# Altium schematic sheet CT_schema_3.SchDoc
size 283 x 173 mm
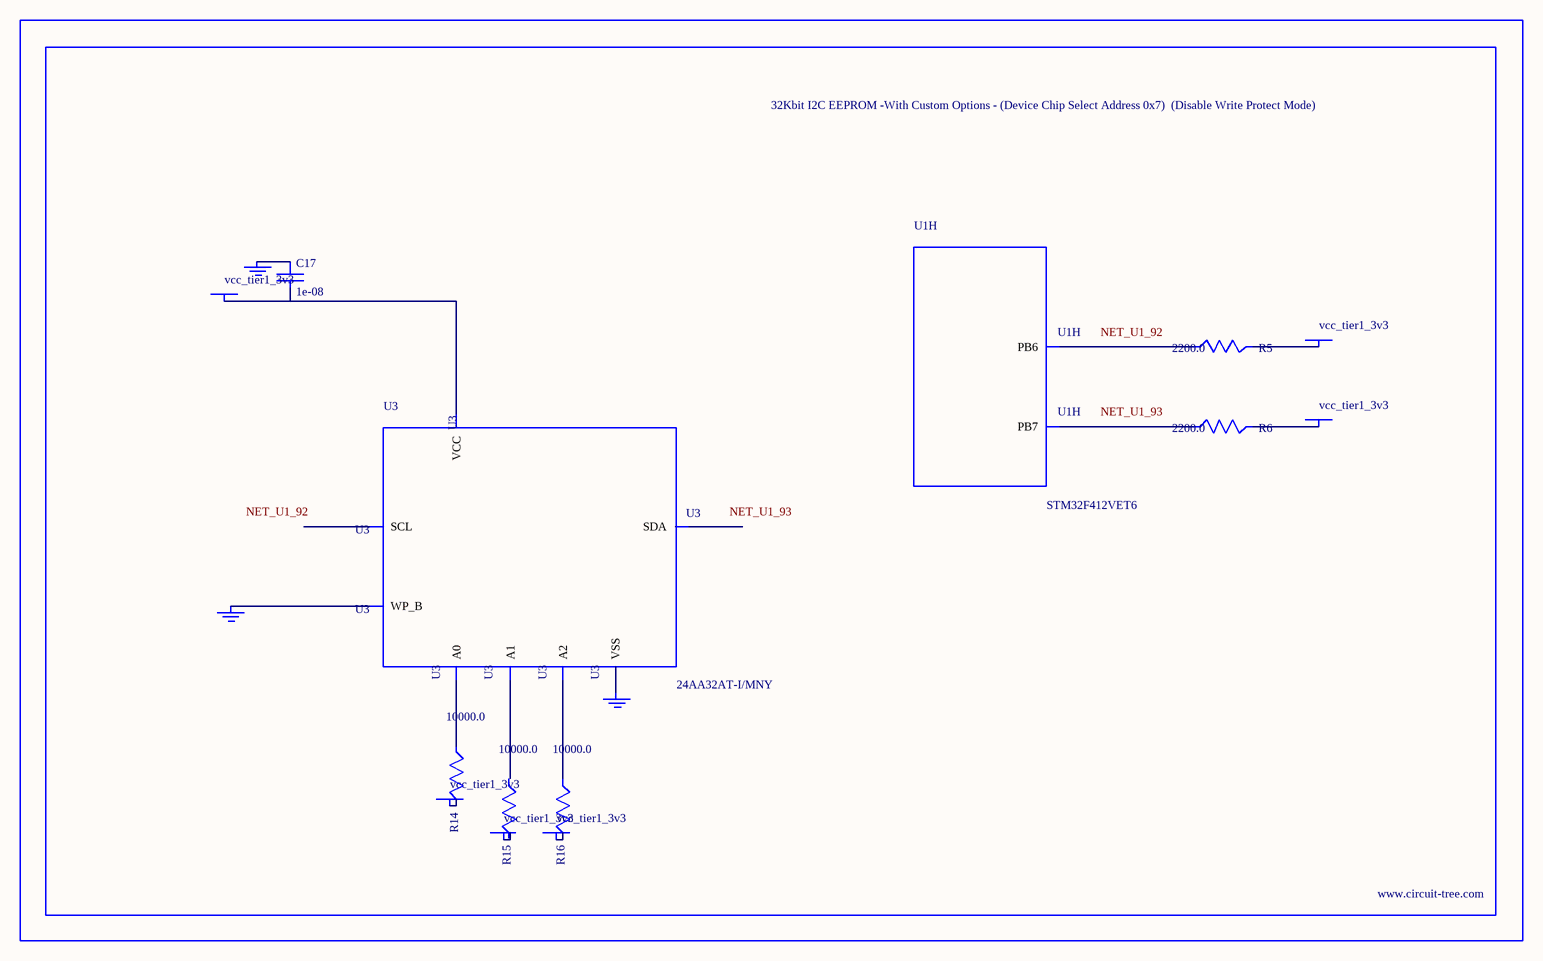
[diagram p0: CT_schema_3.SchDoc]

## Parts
BORDER2  (no value)
C17  1e-08  [C0402]
GND_INSTANCE_2_0  (no value)
GND_INSTANCE_2_1  (no value)
GND_INSTANCE_2_2  (no value)
POWER_INSTANCE_2_0  vcc_tier1_3v3
POWER_INSTANCE_2_1  vcc_tier1_3v3
POWER_INSTANCE_2_2  vcc_tier1_3v3
POWER_INSTANCE_2_3  vcc_tier1_3v3
POWER_INSTANCE_2_4  vcc_tier1_3v3
POWER_INSTANCE_2_5  vcc_tier1_3v3
R5  2200.0  [R0603]
R6  2200.0  [R0603]
R14  10000.0  [R0603]
R15  10000.0  [R0603]
R16  10000.0  [R0603]
U1  STM32F412VET6  [LQFP100]  (part H of 9)
U3  24AA32AT-I/MNY  [TDFN-8/6MM]

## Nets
NetC17_1: C17.1 GND_INSTANCE_2_1.0(GND)
NetC17_2: C17.2 POWER_INSTANCE_2_3.0(PWR) U3.8(VCC)
NetGND_INSTANCE_2_0_0: GND_INSTANCE_2_0.0(GND) U3.7(WP_B)
NetGND_INSTANCE_2_2_0: GND_INSTANCE_2_2.0(GND) U3.4(VSS)
NetPOWER_INSTANCE_2_0_0: POWER_INSTANCE_2_0.0(PWR) R14.2
NetPOWER_INSTANCE_2_2_0: POWER_INSTANCE_2_2.0(PWR) R16.2
NetPOWER_INSTANCE_2_4_0: POWER_INSTANCE_2_4.0(PWR) R5.2
NetPOWER_INSTANCE_2_5_0: POWER_INSTANCE_2_5.0(PWR) R6.2
NetR5_1: R5.1 U1.92(PB6)
NetR6_1: R6.1 U1.93(PB7)
NetR14_1: R14.1 U3.1(A0)
NetR16_1: R16.1 U3.3(A2)

Not connected (* = marked no-connect by the designer): POWER_INSTANCE_2_1 0(PWR); R15 1 2; U3 2(A1) 5(SDA) 6(SCL)

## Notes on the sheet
- Labels drawn without touching a wire or pin: NET_U1_92, NET_U1_93

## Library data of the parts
BORDER2 = BORDER_PAGE2
C17 = C0402C103K3RAC
GND_INSTANCE_2_0-GND_INSTANCE_2_2 = GND
POWER_INSTANCE_2_0-POWER_INSTANCE_2_5 = PWR
R5 R6 = RC0603JR-072K2L
R14-R16 = RC0603JR-0710KL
